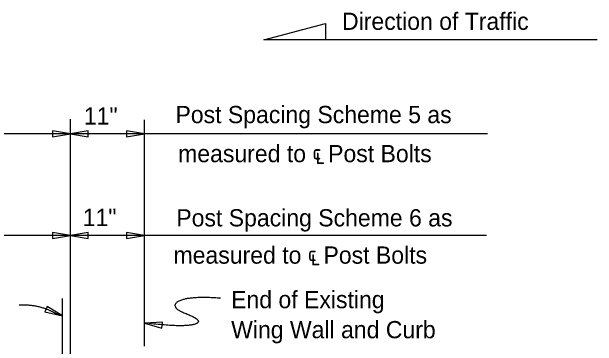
# Model space of a CAD drawing. Extents: x 21587 to 21659.1, y 56116.2 to 56157.3.
# Drawn here: x 21619.3 to 21626.16, y 56138.76 to 56142.68 of the extents above; entities that cross this region are included whole.
import ezdxf

# ---------------------------------------------------------------- set-up
doc = ezdxf.new("R2010")
doc.units = 0
for name, color, linetype in [('PlotBorder_dp', 7, 'Continuous'), ('SheetBorder_dp', 7, 'Continuous'), ('TextMisc', 7, 'Continuous')]:
    doc.layers.add(name, color=color, linetype=linetype)

msp = doc.modelspace()

# ---------------------------------------------------------------- linework, layer by layer
at = {"layer": 'PlotBorder_dp'}
for p, q in [((21622.2503, 56142.3504), (21622.9719, 56142.542)), ((21622.9719, 56142.542), (21622.9736, 56142.3504)), ((21626.1583, 56142.3504), (21622.2503, 56142.3504)), ((21620.8499, 56138.765), (21620.8499, 56141.4148)), ((21624.8732, 56141.2515), (21608.858, 56141.2515)), ((21624.8601, 56140.0606), (21608.858, 56140.0606))]:
    msp.add_line(p, q, dxfattribs=at)
for points in [[(21619.9831, 56141.2515), (21619.7748, 56141.2867), (21619.7748, 56141.2162)], [(21619.9831, 56141.2515), (21620.1913, 56141.2162), (21620.1913, 56141.2867)], [(21620.8499, 56141.2515), (21620.6416, 56141.2867), (21620.6416, 56141.2162)], [(21619.9831, 56140.0605), (21619.7748, 56140.0958), (21619.7748, 56140.0252)], [(21619.9831, 56140.0605), (21620.1913, 56140.0252), (21620.1913, 56140.0958)], [(21620.8499, 56140.0605), (21620.6416, 56140.0958), (21620.6416, 56140.0252)], [(21619.8893, 56139.1192), (21619.7096, 56139.2302), (21619.683, 56139.1648)], [(21620.8527, 56139.0352), (21621.0553, 56138.9756), (21621.0636, 56139.0457)]]:
    msp.add_lwpolyline(points, close=True, dxfattribs=at)
for points in [[(21621.7439, 56139.3253), (21621.3655, 56139.353), (21621.1329, 56139.2245), (21621.5634, 56139.0578), (21621.3065, 56138.9813), (21620.8526, 56139.0353)], [(21619.3819, 56139.2502), (21619.5244, 56139.2502), (21619.7034, 56139.2038), (21619.8194, 56139.1441), (21619.8893, 56139.1192)]]:
    msp.add_open_spline(points, degree=2, dxfattribs=at)
at = {"layer": 'TextMisc'}
for p, q in [((21619.9831, 56136.3623), (21619.9831, 56141.4203)), ((21619.8893, 56136.9565), (21619.8893, 56139.3215))]:
    msp.add_line(p, q, dxfattribs=at)

# ---------------------------------------------------------------- texts
at = {"layer": 'PlotBorder_dp'}
for s, p in [('End of Existing', (21621.8671, 56139.2089)), ('Wing Wall and Curb', (21621.8671, 56138.8569))]:
    msp.add_text(s, height=0.2016, dxfattribs=at).set_placement(p)
at = {"layer": 'SheetBorder_dp'}
msp.add_text('Direction of Traffic', height=0.2016, rotation=359.99977, dxfattribs=at).set_placement((21623.1668, 56142.4673))
for s, p in [('11"', (21620.1411, 56141.3591)), ('Post Spacing Scheme 5 as', (21621.2147, 56141.3752)), ('measured to ℄ Post Bolts', (21621.2461, 56140.9182)), ('11"', (21620.1278, 56140.1706)), ('Post Spacing Scheme 6 as', (21621.2246, 56140.1663)), ('measured to ℄ Post Bolts', (21621.1918, 56139.7301))]:
    msp.add_text(s, height=0.2016, dxfattribs=at).set_placement(p)

doc.saveas('drawing.dxf')
